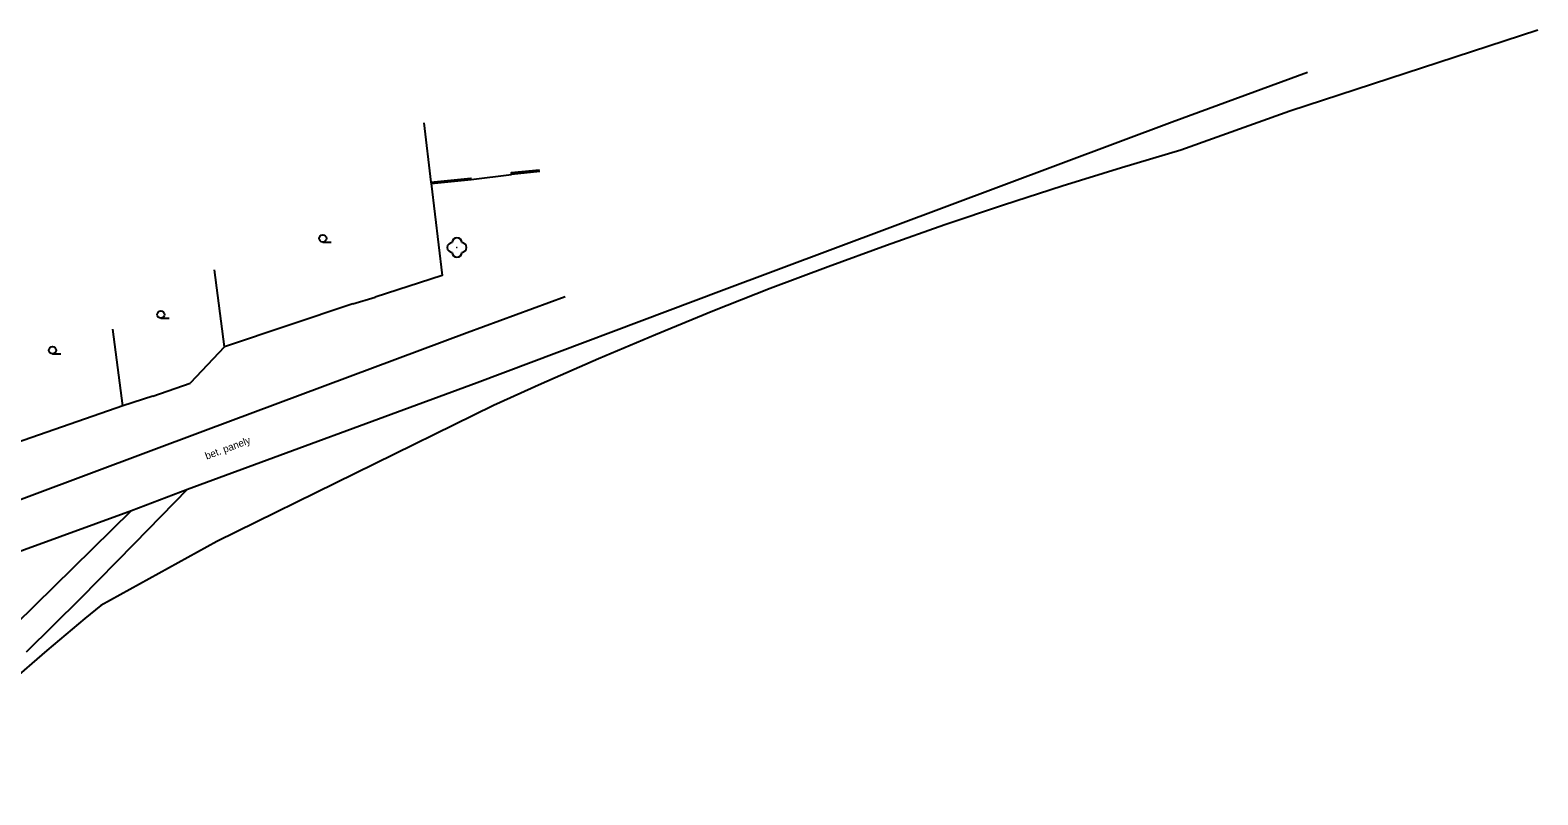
# Model space of a CAD drawing. Extents: x -544674 to -541478, y -1199076 to -1195527.
# Drawn here: x -541633.5 to -541478, y -1198980.6 to -1198901.8 of the extents above; entities that cross this region are included whole.
import ezdxf

# ---------------------------------------------------------------- set-up
doc = ezdxf.new("R2010")
doc.units = 0
for name, color, linetype in [('POMOC_POPIS', 7, 'Continuous'), ('ROZHRANÍ_PLOCH', 7, 'Continuous'), ('ZELEŇ', 7, 'Continuous'), ('ZN_DOPLŇKOVÉ', 7, 'Continuous'), ('ZN_KULTUR', 7, 'Continuous')]:
    doc.layers.add(name, color=color, linetype=linetype)

msp = doc.modelspace()

# ---------------------------------------------------------------- linework, layer by layer
at = {"layer": 'ROZHRANÍ_PLOCH'}
for points in [[(-541617.24, -1198949.1), (-541587.38, -1198938.12), (-541562.19, -1198928.61), (-541515.72, -1198911.22), (-541501.78, -1198906.1)], [(-541653.79, -1198955.77), (-541651.71, -1198955.4), (-541649.22, -1198954.88), (-541646.76, -1198954.29), (-541644.31, -1198953.61), (-541641.89, -1198952.87), (-541639.49, -1198952.04), (-541615.4, -1198943.03), (-541588.42, -1198932.96), (-541578.29, -1198929.24)], [(-541617.24, -1198949.1), (-541622.73, -1198954.76), (-541628.27, -1198960.37), (-541633.87, -1198965.91)], [(-541623.03, -1198951.32), (-541617.24, -1198949.1)], [(-541672.91, -1198961.58), (-541668.64, -1198961.71), (-541668.07, -1198961.72), (-541665.37, -1198961.7), (-541662.67, -1198961.61), (-541659.98, -1198961.44), (-541657.29, -1198961.19), (-541654.62, -1198960.85), (-541651.95, -1198960.44), (-541649.3, -1198959.95), (-541646.66, -1198959.38), (-541644.04, -1198958.73), (-541641.44, -1198958.01), (-541623.03, -1198951.32)], [(-541652.88, -1198980.64), (-541623.03, -1198951.32)]]:
    msp.add_lwpolyline(points, dxfattribs=at)
at = {"layer": 'ZELEŇ'}
msp.add_circle((-541589.46, -1198924.18), 0.0005, dxfattribs=at)
for centre, start, end in [((-541589.46, -1198923.68), 0, 179.99999), ((-541589.96, -1198924.18), 89.99999, 269.99999), ((-541589.46, -1198924.68), 179.99999, 359.99999), ((-541588.96, -1198924.18), 270, 89.99999)]:
    msp.add_arc(centre, 0.5, start, end, dxfattribs=at)
at = {"layer": 'ZN_DOPLŇKOVÉ'}
for points in [[(-541478.02, -1198901.76), (-541503.6, -1198910.13), (-541514.83, -1198914.15), (-541520.95, -1198915.96), (-541527.05, -1198917.85), (-541533.12, -1198919.81), (-541539.17, -1198921.85), (-541545.19, -1198923.97), (-541551.19, -1198926.16), (-541557.16, -1198928.42), (-541563.09, -1198930.76), (-541569, -1198933.18), (-541574.88, -1198935.67), (-541580.73, -1198938.23), (-541585.69, -1198940.47), (-541614.21, -1198954.51), (-541626.18, -1198961.1), (-541627.81, -1198962.44), (-541631.75, -1198965.75), (-541635.64, -1198969.13)], [(-541592.87, -1198911.32), (-541592.14, -1198917.44)], [(-541592.14, -1198917.44), (-541588.02, -1198917.02), (-541588, -1198917.17)], [(-541588, -1198917.17), (-541583.85, -1198916.64)], [(-541580.95, -1198916.2), (-541583.87, -1198916.49), (-541583.85, -1198916.64)], [(-541580.93, -1198916.35), (-541583.85, -1198916.64)], [(-541592.12, -1198917.59), (-541590.99, -1198927.08), (-541597.9, -1198929.29)], [(-541592.14, -1198917.44), (-541592.12, -1198917.59)], [(-541592.12, -1198917.59), (-541588, -1198917.17)], [(-541613.44, -1198934.41), (-541614.46, -1198926.5)], [(-541600.2, -1198929.99), (-541597.9, -1198929.29)], [(-541600.2, -1198929.99), (-541613.44, -1198934.41)], [(-541623.92, -1198940.52), (-541634.88, -1198944.33), (-541636.22, -1198932.61)], [(-541623.92, -1198940.52), (-541624.94, -1198932.61)], [(-541613.44, -1198934.41), (-541616.96, -1198938.17)], [(-541620.81, -1198939.53), (-541616.96, -1198938.17)], [(-541620.81, -1198939.53), (-541623.92, -1198940.52)]]:
    msp.add_lwpolyline(points, dxfattribs=at)
at = {"layer": 'ZN_KULTUR'}
for p, q in [((-541603.3, -1198923.615), (-541602.425, -1198923.615)), ((-541619.99, -1198931.475), (-541619.115, -1198931.475)), ((-541631.16, -1198935.155), (-541630.285, -1198935.155))]:
    msp.add_line(p, q, dxfattribs=at)
for centre in [(-541603.3, -1198923.24), (-541619.99, -1198931.1), (-541631.16, -1198934.78)]:
    msp.add_circle(centre, 0.375, dxfattribs=at)

# ---------------------------------------------------------------- texts
at = {"layer": 'POMOC_POPIS'}
msp.add_text('bet. panely', height=0.75, rotation=20.51, dxfattribs=at).set_placement((-541615.26, -1198946.07))

doc.saveas('drawing.dxf')
